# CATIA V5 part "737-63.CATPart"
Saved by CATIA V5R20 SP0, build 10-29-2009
Part number: 737-63
Definition: NONE
Nomenclature: 737-63
Source: Unknown
Description: 737-63
Bounding box of the stored display mesh (mm): x -60 to 46, y -59.896 to 59.896, z -60 to 42
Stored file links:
  C:\Users\Utente\Desktop\IO LAVORO\3D X SITO CF\X SITO\737\737-63.CATPart
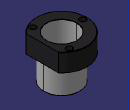
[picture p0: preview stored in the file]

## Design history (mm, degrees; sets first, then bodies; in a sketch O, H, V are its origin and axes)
Body1 "737-63" (main body)
  Solid1: solid without history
